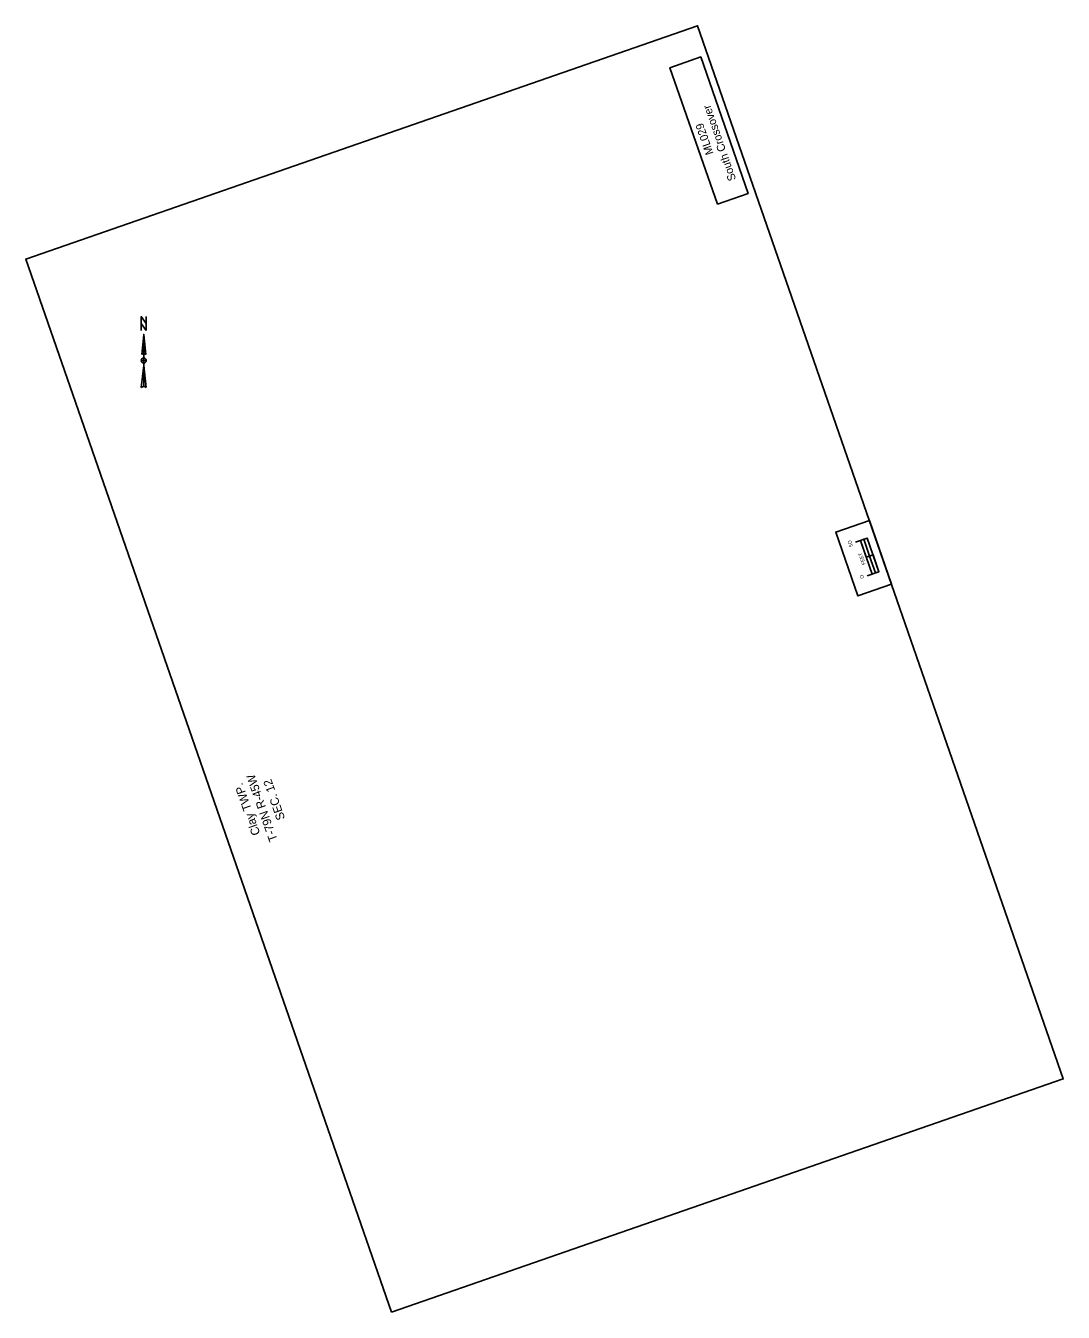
# Model space of a CAD drawing. Extents: x 16415719 to 16419955, y 7114623 to 7121273.
# Drawn here: x 16417400 to 16418859, y 7114623 to 7116432 of the extents above; entities that cross this region are included whole.
import ezdxf

# ---------------------------------------------------------------- set-up
doc = ezdxf.new("R2010")
doc.units = 0
for name, color, linetype in [('NamedBoundary', 7, 'Continuous'), ('SheetBorder', 7, 'Continuous'), ('SheetGridMajor', 7, 'Continuous')]:
    doc.layers.add(name, color=color, linetype=linetype)

msp = doc.modelspace()

# ---------------------------------------------------------------- linework, layer by layer
at = {"layer": 'NamedBoundary'}
msp.add_lwpolyline([(16417914.4, 7114623), (16418859.1, 7114951.1), (16418344.8, 7116431.8), (16417400.2, 7116103.7)], close=True, dxfattribs=at)
at = {"layer": 'SheetBorder'}
msp.add_line((16418591.6, 7115687.8), (16418582.1, 7115684.6), dxfattribs=at)
msp.add_line((16418591.6, 7115687.8), (16418582.1, 7115684.6), dxfattribs=at)
for points in [[(16418372.7, 7116180.8), (16418306, 7116372.8), (16418349.3, 7116387.9), (16418416, 7116195.8)], [(16418570.3, 7115630.2), (16418539.1, 7115719.9), (16418586.4, 7115736.3), (16418617.5, 7115646.6)], [(16418570.3, 7115630.2), (16418539.1, 7115719.9), (16418586.4, 7115736.3), (16418617.5, 7115646.6)], [(16418617.5, 7115646.6), (16418570.3, 7115630.2), (16418539.1, 7115719.9), (16418586.4, 7115736.3)], [(16418586.8, 7115686.2), (16418578.6, 7115709.8), (16418573.9, 7115708.2), (16418582.1, 7115684.6)], [(16418599.8, 7115664.2), (16418591.6, 7115687.8), (16418586.8, 7115686.2), (16418595, 7115662.6)]]:
    msp.add_lwpolyline(points, close=True, dxfattribs=at)
for points in [[(16418583.2, 7115658.5), (16418599.8, 7115664.2), (16418583.4, 7115711.5), (16418566.8, 7115705.7)], [(16418590.3, 7115660.9), (16418573.9, 7115708.2)]]:
    msp.add_lwpolyline(points, dxfattribs=at)
at = {"layer": 'SheetGridMajor'}
for p, q in [((16417566.1, 7115997.7), (16417568.9, 7115969.5)), ((16417566.1, 7115997.7), (16417566.1, 7115924.4)), ((16417563.3, 7115969.5), (16417563.3, 7115969.5)), ((16417563.4, 7115969.8), (16417563.9, 7115970.4)), ((16417562.6, 7115923), (16417566.1, 7115954)), ((16417566.1, 7115957.5), (16417566.1, 7115957.5))]:
    msp.add_line(p, q, dxfattribs=at)
msp.add_lwpolyline([(16417569.7, 7116003.3), (16417562.6, 7116013.2), (16417562.6, 7116023), (16417569.7, 7116013.2)], close=True, dxfattribs=at)
for points in [[(16417562.6, 7116003.3), (16417562.6, 7116023), (16417569.7, 7116013.2), (16417569.7, 7116023)], [(16417563.3, 7115969.5), (16417566.1, 7115997.7), (16417566.1, 7115970.9)], [(16417569.7, 7115961.1), (16417566.1, 7115961.1), (16417566.1, 7115964.6)], [(16417566.1, 7115957.5), (16417566.1, 7115961.1), (16417562.6, 7115961.1)], [(16417566.1, 7115924.4), (16417566.1, 7115954), (16417569.7, 7115923)]]:
    msp.add_lwpolyline(points, dxfattribs=at)
for centre, radius, start, end in [((16417566.1, 7115961.1), 3.52, 89.9997, 179.9997), ((16417566.1, 7115967.4), 3.52, 90.0201, 143.1255), ((16417566.1, 7115967.4), 3.52, 36.8478, 90.0216), ((16417566.1, 7115961.1), 3.52, 359.9997, 89.9997), ((16417566.1, 7115961.1), 3.52, 179.9997, 269.9997), ((16417566.1, 7115961.1), 3.52, 269.9997, 359.9997), ((16417566.1, 7115919.3), 5.1, 89.9891, 133.6187), ((16417566.1, 7115919.3), 5.11, 46.4018, 90.0004)]:
    msp.add_arc(centre, radius, start, end, dxfattribs=at)

# ---------------------------------------------------------------- texts
at = {"layer": 'SheetBorder'}
for s, height, rotation, p in [('South Crossover', 11.25, 109.1528, (16418399.2, 7116215.8)), ('ML029 ', 11.25, 109.1528, (16418367.4, 7116252.5)), ('5O', 5, 109.1528, (16418563.4, 7115700.2)), ('FEET', 5, 109.1528, (16418581.3, 7115674.8)), ('O', 5, 109.1528, (16418579, 7115655.3)), ('Clay TWP.', 12, 109.415, (16417730.1, 7115295.9)), ('T-79N R-45W', 12, 109.415, (16417754.4, 7115287.2)), ('SEC. 12', 12, 109.415, (16417765, 7115317.3))]:
    msp.add_text(s, height=height, rotation=rotation, dxfattribs=at).set_placement(p)

doc.saveas('drawing.dxf')
